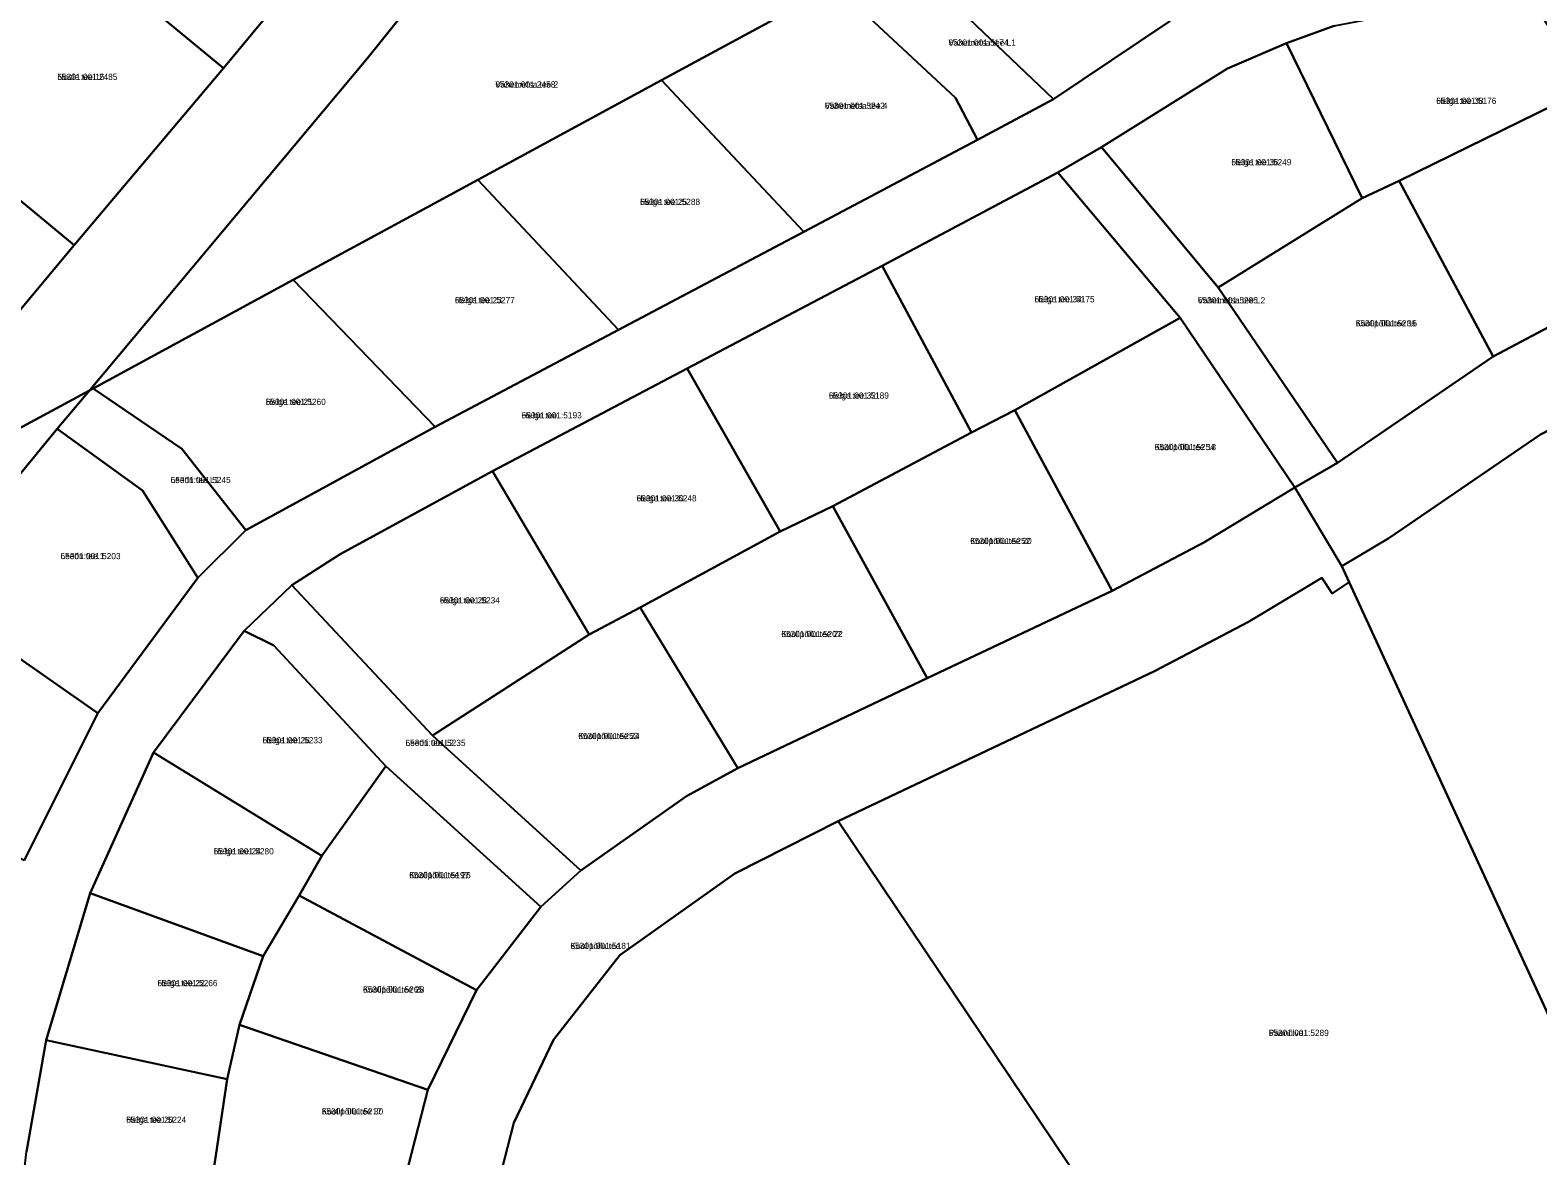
# Model space of a CAD drawing. Extents: x 543236 to 563717, y 6566033 to 6588992.
# Drawn here: x 546570 to 546934.3, y 6582526.2 to 6582798.1 of the extents above; entities that cross this region are included whole.
import ezdxf

# ---------------------------------------------------------------- set-up
doc = ezdxf.new("R2010")
doc.units = 0
for name, color, linetype in [('L_AADRESS', 7, 'Continuous'), ('PIIR', 7, 'Continuous'), ('TUNNUS', 7, 'Continuous')]:
    doc.layers.add(name, color=color, linetype=linetype)

msp = doc.modelspace()

# ---------------------------------------------------------------- linework, layer by layer
at = {"layer": 'PIIR'}
for points in [[(546529.46, 6582861.05), (546539.65, 6582873.39), (546582.05, 6582838.36), (546626.94, 6582801.27), (546616.68, 6582788.99), (546571.86, 6582826.02)], [(546704.61, 6582857.46), (546764.57, 6582808.86), (546722.52, 6582786.05), (546678.14, 6582762.03), (546665.85, 6582755.32), (546633.59, 6582737.86), (546585.24, 6582711.61), (546584.34, 6582711.11), (546651.49, 6582791.37)], [(546817.24, 6582781.51), (546779.87, 6582817.15), (546802.52, 6582829.41), (546823.73, 6582840.99), (546845.35, 6582800.32)], [(546536.23, 6582782.9), (546571.86, 6582826.02), (546616.68, 6582788.99), (546580.62, 6582746.23), (546539.15, 6582780.49)], [(546793.59, 6582781.78), (546764.57, 6582808.86), (546779.87, 6582817.15), (546817.24, 6582781.51), (546798.93, 6582771.65)], [(546756.97, 6582749.43), (546722.52, 6582786.05), (546764.57, 6582808.86), (546793.59, 6582781.78), (546798.93, 6582771.65)], [(546891.86, 6582757.53), (546873.6, 6582795.04), (546885.11, 6582799.19), (546893.51, 6582800.81), (546934.26, 6582803.13), (546946.5, 6582784.11), (546900.82, 6582761.74)], [(546857.09, 6582735.98), (546828.9, 6582769.86), (546859.35, 6582788.9), (546873.6, 6582795.04), (546891.86, 6582757.53)], [(546712.19, 6582725.8), (546678.14, 6582762.03), (546722.52, 6582786.05), (546756.97, 6582749.43)], [(546923.51, 6582719.34), (546900.82, 6582761.74), (546946.5, 6582784.11), (546948.14, 6582784.9), (546966.85, 6582742.28)], [(546513.45, 6582749.39), (546539.15, 6582780.49), (546580.62, 6582746.23), (546567.28, 6582730.2), (546557, 6582738.69), (546522.04, 6582742.29), (546517.18, 6582746.3)], [(546886.93, 6582668.71), (546875.55, 6582687.65), (546885.92, 6582693.62), (546923.51, 6582719.34), (546966.85, 6582742.28), (547009.23, 6582759.43), (547048.33, 6582771.25), (547072.7, 6582775.5), (547089.28, 6582762.64), (547196.89, 6582497.6), (547178.77, 6582490.41), (547172.43, 6582500.1), (547161.38, 6582502.28), (547151.61, 6582524.55), (547157.46, 6582527.22), (547162.53, 6582539.69), (547081.57, 6582739.21), (547067.72, 6582747.19), (547054.35, 6582750.09), (547016.58, 6582738.62), (546981.53, 6582724.46), (546934.93, 6582700.48), (546898.3, 6582675.45)], [(546847.87, 6582728.68), (546818.35, 6582763.8), (546828.9, 6582769.86), (546857.09, 6582735.98), (546885.92, 6582693.62), (546875.55, 6582687.65)], [(546797.47, 6582701), (546775.88, 6582741.26), (546818.35, 6582763.8), (546847.87, 6582728.68), (546807.89, 6582706.35)], [(546667.89, 6582702.36), (546633.59, 6582737.86), (546665.85, 6582755.32), (546678.14, 6582762.03), (546712.19, 6582725.8)], [(546885.92, 6582693.62), (546857.09, 6582735.98), (546891.86, 6582757.53), (546900.82, 6582761.74), (546923.51, 6582719.34)], [(546888.74, 6582664.77), (546886.93, 6582668.71), (546898.3, 6582675.45), (546934.93, 6582700.48), (546981.53, 6582724.46), (547016.58, 6582738.62), (547054.35, 6582750.09), (547067.72, 6582747.19), (547081.57, 6582739.21), (547162.53, 6582539.69), (547157.46, 6582527.22), (547151.61, 6582524.55), (547074.22, 6582488.92), (547035.55, 6582469.01), (547019, 6582459.52), (546995.62, 6582442.62), (546973.31, 6582487.08), (546939.47, 6582554.58)], [(546751.19, 6582677.02), (546728.73, 6582716.45), (546775.88, 6582741.26), (546797.47, 6582701), (546763.92, 6582683.17)], [(546606.61, 6582697), (546585.24, 6582711.61), (546633.59, 6582737.86), (546667.89, 6582702.36), (546622.12, 6582677.4)], [(546831.45, 6582662.75), (546807.89, 6582706.35), (546847.87, 6582728.68), (546875.55, 6582687.65), (546853.62, 6582674.4)], [(546705.07, 6582652.2), (546681.72, 6582691.61), (546728.73, 6582716.45), (546751.19, 6582677.02), (546717.38, 6582658.66)], [(546597.18, 6582686.98), (546576.53, 6582701.85), (546584.34, 6582711.11), (546585.24, 6582711.61), (546606.61, 6582697), (546622.12, 6582677.4), (546610.48, 6582665.87)], [(546786.73, 6582641.66), (546763.92, 6582683.17), (546797.47, 6582701), (546807.89, 6582706.35), (546831.45, 6582662.75)], [(546586.34, 6582633.2), (546544.2, 6582662.55), (546576.53, 6582701.85), (546597.18, 6582686.98), (546610.48, 6582665.87)], [(546667.18, 6582627.75), (546633.23, 6582664.07), (546644.87, 6582671.59), (546681.72, 6582691.61), (546705.07, 6582652.2)], [(546741.03, 6582619.91), (546717.38, 6582658.66), (546751.19, 6582677.02), (546763.92, 6582683.17), (546786.73, 6582641.66)], [(546879.85, 6582436.5), (546765.27, 6582607.08), (546841.69, 6582643.31), (546864.37, 6582655.22), (546882.15, 6582665.86), (546884.57, 6582662.08), (546888.74, 6582664.77), (546939.47, 6582554.58), (546973.31, 6582487.08)], [(546568.57, 6582597.54), (546514.76, 6582626.66), (546544.2, 6582662.55), (546586.34, 6582633.2)], [(546628.89, 6582649.54), (546621.75, 6582653.04), (546633.23, 6582664.07), (546667.18, 6582627.75), (546703.08, 6582595.15), (546693.38, 6582586.4), (546655.98, 6582620.35)], [(546703.08, 6582595.15), (546667.18, 6582627.75), (546705.07, 6582652.2), (546717.38, 6582658.66), (546741.03, 6582619.91), (546728.61, 6582613.12)], [(546599.8, 6582623.64), (546621.75, 6582653.04), (546628.89, 6582649.54), (546655.98, 6582620.35), (546640.51, 6582598.74)], [(546584.49, 6582589.66), (546599.8, 6582623.64), (546640.51, 6582598.74), (546635.04, 6582589.13), (546626.29, 6582574.48)], [(546640.51, 6582598.74), (546655.98, 6582620.35), (546693.38, 6582586.4), (546677.86, 6582566.25), (546635.04, 6582589.13)], [(546716.7, 6582460.13), (546680.05, 6582507.56), (546686.86, 6582534.18), (546696.47, 6582554.28), (546712.51, 6582574.73), (546740.26, 6582594.42), (546765.27, 6582607.08), (546879.85, 6582436.5), (546930.94, 6582360.4), (547136.57, 6582054.14), (547110.44, 6582033.94), (547097.7, 6582024.11), (547070.09, 6582002.79)], [(546573.84, 6582554.21), (546584.49, 6582589.66), (546626.29, 6582574.48), (546620.59, 6582557.86), (546617.63, 6582544.78)], [(546626.29, 6582574.48), (546635.04, 6582589.13), (546677.86, 6582566.25), (546666.1, 6582542.19), (546620.59, 6582557.86)], [(546617.63, 6582544.78), (546620.59, 6582557.86), (546666.1, 6582542.19), (546659.04, 6582514.59), (546614.34, 6582522.53)], [(546569.11, 6582527.18), (546573.84, 6582554.21), (546617.63, 6582544.78), (546614.34, 6582522.53), (546613.33, 6582514.21), (546568.17, 6582519.01)]]:
    msp.add_lwpolyline(points, close=True, dxfattribs=at)
for points in [[(546704.61, 6582857.46), (546651.49, 6582791.37), (546584.34, 6582711.11), (546540.83, 6582687.7)], [(546567.28, 6582730.2), (546580.62, 6582746.23), (546616.68, 6582788.99), (546626.94, 6582801.27)], [(546568.57, 6582597.54), (546586.34, 6582633.2), (546610.48, 6582665.87), (546622.12, 6582677.4), (546667.89, 6582702.36), (546712.19, 6582725.8), (546756.97, 6582749.43), (546798.93, 6582771.65), (546817.24, 6582781.51), (546845.35, 6582800.32)], [(546885.11, 6582799.19), (546873.6, 6582795.04), (546859.35, 6582788.9), (546828.9, 6582769.86), (546818.35, 6582763.8), (546775.88, 6582741.26), (546728.73, 6582716.45), (546681.72, 6582691.61), (546644.87, 6582671.59), (546633.23, 6582664.07), (546621.75, 6582653.04), (546599.8, 6582623.64), (546584.49, 6582589.66), (546573.84, 6582554.21), (546569.11, 6582527.18)], [(546399.94, 6582520.95), (546409.21, 6582532.3), (546406.78, 6582535.23), (546470.31, 6582612.55), (546525.43, 6582679.33), (546540.83, 6582687.7), (546584.34, 6582711.11), (546576.53, 6582701.85), (546544.2, 6582662.55), (546514.76, 6582626.66), (546484.86, 6582590.34), (546480.96, 6582582), (546465.48, 6582544.58), (546455.61, 6582501.78)], [(546659.04, 6582514.59), (546666.1, 6582542.19), (546677.86, 6582566.25), (546693.38, 6582586.4), (546703.08, 6582595.15), (546728.61, 6582613.12), (546741.03, 6582619.91), (546786.73, 6582641.66), (546831.45, 6582662.75), (546853.62, 6582674.4), (546875.55, 6582687.65), (546886.93, 6582668.71), (546888.74, 6582664.77), (546884.57, 6582662.08), (546882.15, 6582665.86), (546864.37, 6582655.22), (546841.69, 6582643.31), (546765.27, 6582607.08), (546740.26, 6582594.42), (546712.51, 6582574.73), (546696.47, 6582554.28), (546686.86, 6582534.18), (546680.05, 6582507.56)]]:
    msp.add_lwpolyline(points, dxfattribs=at)

# ---------------------------------------------------------------- texts
at = {"layer": 'L_AADRESS'}
for s, p in [('Vahemetsa tee L1', (546791.9, 6582794.4)), ('Noole tee 16', (546576.58, 6582786.12)), ('Vahemetsa tee 2', (546682.41, 6582784.29)), ('Helge tee 38', (546909.77, 6582780.33)), ('Vahemetsa tee 4', (546762, 6582779.15)), ('Helge tee 36', (546860.25, 6582765.51)), ('Helge tee 25', (546717.37, 6582755.93)), ('Helge tee 34', (546812.69, 6582732.4)), ('Helge tee 23', (546672.62, 6582732.2)), ('Vahemetsa tee L2', (546852.14, 6582732.15)), ('Koolipõllu tee 16', (546890.3, 6582726.59)), ('Helge tee 21', (546626.93, 6582707.63)), ('Helge tee 32', (546763, 6582709.14)), ('Helge tee', (546688.77, 6582704.37)), ('Koolipõllu tee 18', (546841.72, 6582696.7)), ('Leedri tee L1', (546603.94, 6582688.74)), ('Helge tee 30', (546716.53, 6582684.32)), ('Koolipõllu tee 20', (546797.16, 6582674.01)), ('Leedri tee 1', (546577.34, 6582670.37)), ('Helge tee 28', (546668.99, 6582659.68)), ('Koolipõllu tee 22', (546751.51, 6582651.54)), ('Koolipõllu tee 24', (546702.44, 6582626.9)), ('Helge tee 26', (546626.16, 6582625.89)), ('Leedri tee L2', (546660.7, 6582625.24)), ('Helge tee 24', (546614.36, 6582599.06)), ('Koolipõllu tee 26', (546661.6, 6582593.3)), ('Koolipõllu tee', (546700.57, 6582576.19)), ('Helge tee 22', (546600.77, 6582567.22)), ('Koolipõllu tee 28', (546650.42, 6582565.66)), ('Paenõlva', (546869.29, 6582555.19)), ('Koolipõllu tee 30', (546640.47, 6582536.23)), ('Helge tee 20', (546593.2, 6582534.21))]:
    msp.add_text(s, height=1.5, dxfattribs=at).set_placement(p)
at = {"layer": 'TUNNUS'}
for s, p in [('65301:001:5174', (546791.9, 6582794.4)), ('65301:001:2485', (546576.58, 6582786.12)), ('65301:001:2458', (546682.41, 6582784.29)), ('65301:001:5176', (546909.77, 6582780.33)), ('65301:001:5242', (546762, 6582779.15)), ('65301:001:5249', (546860.25, 6582765.51)), ('65301:001:5288', (546717.37, 6582755.93)), ('65301:001:5277', (546672.62, 6582732.2)), ('65301:001:5175', (546812.69, 6582732.4)), ('65301:001:5285', (546852.14, 6582732.15)), ('65301:001:5286', (546890.3, 6582726.59)), ('65301:001:5260', (546626.93, 6582707.63)), ('65301:001:5189', (546763, 6582709.14)), ('65301:001:5193', (546688.77, 6582704.37)), ('65301:001:5254', (546841.72, 6582696.7)), ('65301:001:5245', (546603.94, 6582688.74)), ('65301:001:5248', (546716.53, 6582684.32)), ('65301:001:5252', (546797.16, 6582674.01)), ('65301:001:5203', (546577.34, 6582670.37)), ('65301:001:5234', (546668.99, 6582659.68)), ('65301:001:5207', (546751.51, 6582651.54)), ('65301:001:5253', (546702.44, 6582626.9)), ('65301:001:5233', (546626.16, 6582625.89)), ('65301:001:5235', (546660.7, 6582625.24)), ('65301:001:5280', (546614.36, 6582599.06)), ('65301:001:5197', (546661.6, 6582593.3)), ('65301:001:5181', (546700.57, 6582576.19)), ('65301:001:5266', (546600.77, 6582567.22)), ('65301:001:5265', (546650.42, 6582565.66)), ('65301:001:5289', (546869.29, 6582555.19)), ('65301:001:5217', (546640.47, 6582536.23)), ('65301:001:5224', (546593.2, 6582534.21))]:
    msp.add_text(s, height=1.5, dxfattribs=at).set_placement(p)

doc.saveas('drawing.dxf')
